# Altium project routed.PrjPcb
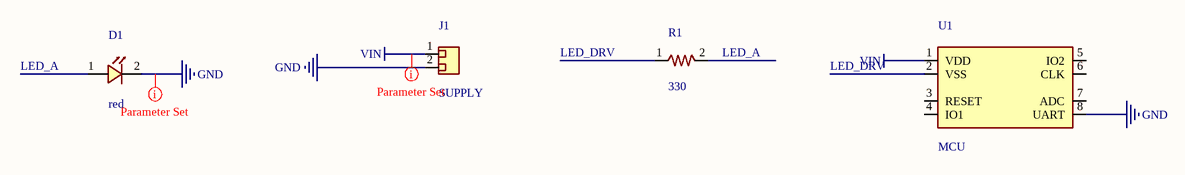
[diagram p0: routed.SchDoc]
1 sheet, 4 parts. Net scope: global (net labels, ports and power ports of the same name join across sheets).
Board file: routed.PcbDoc

## Sheet routed.SchDoc
size A4

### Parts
D1  red  [LED0603_Kingbright_APT1608SURCK]
J1  SUPPLY  [Header_1x2_P2.54]
R1  330  [Chip_0603]
U1  MCU  [DIP8_Microchip_P]

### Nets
GND: D1.2(K) J1.2(Passive) U1.8(UART)
VIN: J1.1(Passive) U1.1(VDD)
LED_A: D1.1(A) R1.2(B)
LED_DRV: R1.1(A) U1.2(VSS)

Not connected (* = marked no-connect by the designer): U1 3(RESET) 4(IO1) 5(IO2) 6(CLK) 7(ADC)

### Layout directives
net class PWR: GND, VIN

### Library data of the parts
D1 = LED: pin to pad: 1>2 2>1
J1 = Connector_2
R1 = Resistor
U1 = Microcontroller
